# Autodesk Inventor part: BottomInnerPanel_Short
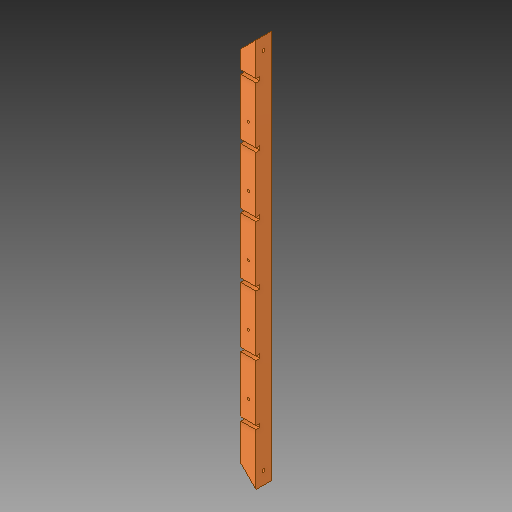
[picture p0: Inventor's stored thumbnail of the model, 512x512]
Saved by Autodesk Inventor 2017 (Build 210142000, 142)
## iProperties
Created: 2017-05
Part Number: BottomInnerPanel_Short
Material: Generic
Document SubType Name: Modeling
Designer: Savy
Density: 1 g/cm^3
Appearance: Default
Mass: 368.978 g
Surface Area: 759.365 cm^2
Volume: 368.978 cm^3
Author: Savy
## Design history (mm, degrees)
feature "SOLID1"
body "Solid1"
